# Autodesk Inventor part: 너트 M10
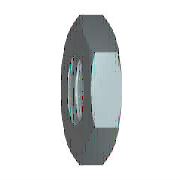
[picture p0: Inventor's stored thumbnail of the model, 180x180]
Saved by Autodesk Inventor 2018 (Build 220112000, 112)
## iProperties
IsCustomPart: 1
Created: 2012-02
Part Number: 너트 M10
Material: 강철, 연강
Description: 6각 가는 너트 - 이중 모따기
Document SubType Name: Modeling
Standard: JIS B 1181
Designer: mduedu
Standards Organization: JIS
Language: ko-KR
Size Designation: A/B M10
Categories: <MemberInstance><Categories><Category DisplayName="조임쇠" InternalName="e4da775c-781d-43d5-af7c-5136215cf5a6" Mnemonic="FSTN"><Category DisplayName="너트" InternalN
Density: 1 g/cm^3
Appearance: 주황색
Author: mduedu
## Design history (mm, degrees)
sketch "스케치1"
  geometry: L1 (-9.238, 0)-(-4.619, 8); L2 (-4.619, 8)-(4.619, 8); L3 (4.619, 8)-(9.238, 0); L4 (9.238, 0)-(4.619, -8); L5 (4.619, -8)-(-4.619, -8); L6 (-4.619, -8)-(-9.238, 0); 2 further points
  constraints: 12 end point, 1 coincident, 1 horizontal, 11 other
  dimensions: "d0" = 18.47521 distance of L3.end L1.start (= 1.1547 x SW)
extrude "본체" new body sketch "스케치1" distance "d1" = 5 (= KOH); taper "d2" = 0 deg
sketch "스케치2"
  geometry: L1 (0, 4.619)-(0, 9.238) reference; L2 (0, 9.238)-(5, 9.238) reference; L3 (5, 4.619)-(5, 9.238) reference; L4 (-1, 0)-(6, 0) reference; L5 (0.715, 9.238)-(0, 8); L6 (4.285, 9.238)-(5, 8)
  constraints: 4 end point, 4 point on line
  dimensions: "d3" = 30 deg angle of L1 L5 (= ANG1); "d4" = 30 deg angle of L3 L6 (= ANG2); "d5" = 16 diameter of L5.end L4 (= SW0); "d6" = 16 diameter of L6.end L4 (= SW01)
revolve "모따기1" sketch "스케치2" stored, may be unused: angle "d7" = 90 deg
sketch "스케치3"
  geometry: A1 r 8 centre (0, 0) between (-4, -6.928) and (4, -6.928) reference; 1 further point
  constraints: 1 coincident
hole "스레드" sketch "스케치3" at (0, 0) diameter "d25" = 8.376; stored, may be unused: countersink angle "d29" = 82 deg, drill point angle "d31" = 118 deg; dims "d26" = 6, "d27" = 4, "d28" = 2, "d30" = 8
workaxis "Work Axis1"
workplane "Work Plane1"
body "Solid1"
chamfer "모따기2" distance "d8" = 0.8119 (= -0.5 x GD1 + 0.5 x NND); stored, may be unused: angle "d9" = 30 deg, second distance "d40" = 0.8119 (= -0.5 x GD1 + 0.5 x NND)
chamfer "모따기3" distance "d10" = 0.8119 (= -0.5 x GD1 + 0.5 x NND); stored, may be unused: angle "d11" = 30 deg, second distance "d41" = 0.8119 (= -0.5 x GD1 + 0.5 x NND)
other parameters: "ANG1" = 30 deg [user parameter; used in 1 equation term], "ANG2" = 30 deg [user parameter; used in 1 equation term], "KOH" = 5 [user parameter; used in 1 equation term], "SW" = 16 [user parameter; used in 4 equation terms], "SW0" = 16 (= SW) [user parameter; used in 1 equation term], "SW01" = 16 (= SW) [user parameter; used in 1 equation term], "GD1" = 8.3762 (computed from THREADDIA, PTC, TOA) [user parameter; used in 4 equation terms], "d13" = 0, "d14" = 0, "d39" = 0, "d42" = 0, "GUL" = 0.8119 (= 0.541266 x PTC) [user parameter], "TPU" = 6.66667 (computed from PTC) [user parameter], "TOA" = 30 deg [user parameter; used in 1 equation term], "PTC" = 1.5 [user parameter; used in 4 equation terms], "E0" = 18.48 (= 1.155 x SW) [user parameter], "GAL" = 0.8119 (= 0.541266 x PTC) [user parameter]
